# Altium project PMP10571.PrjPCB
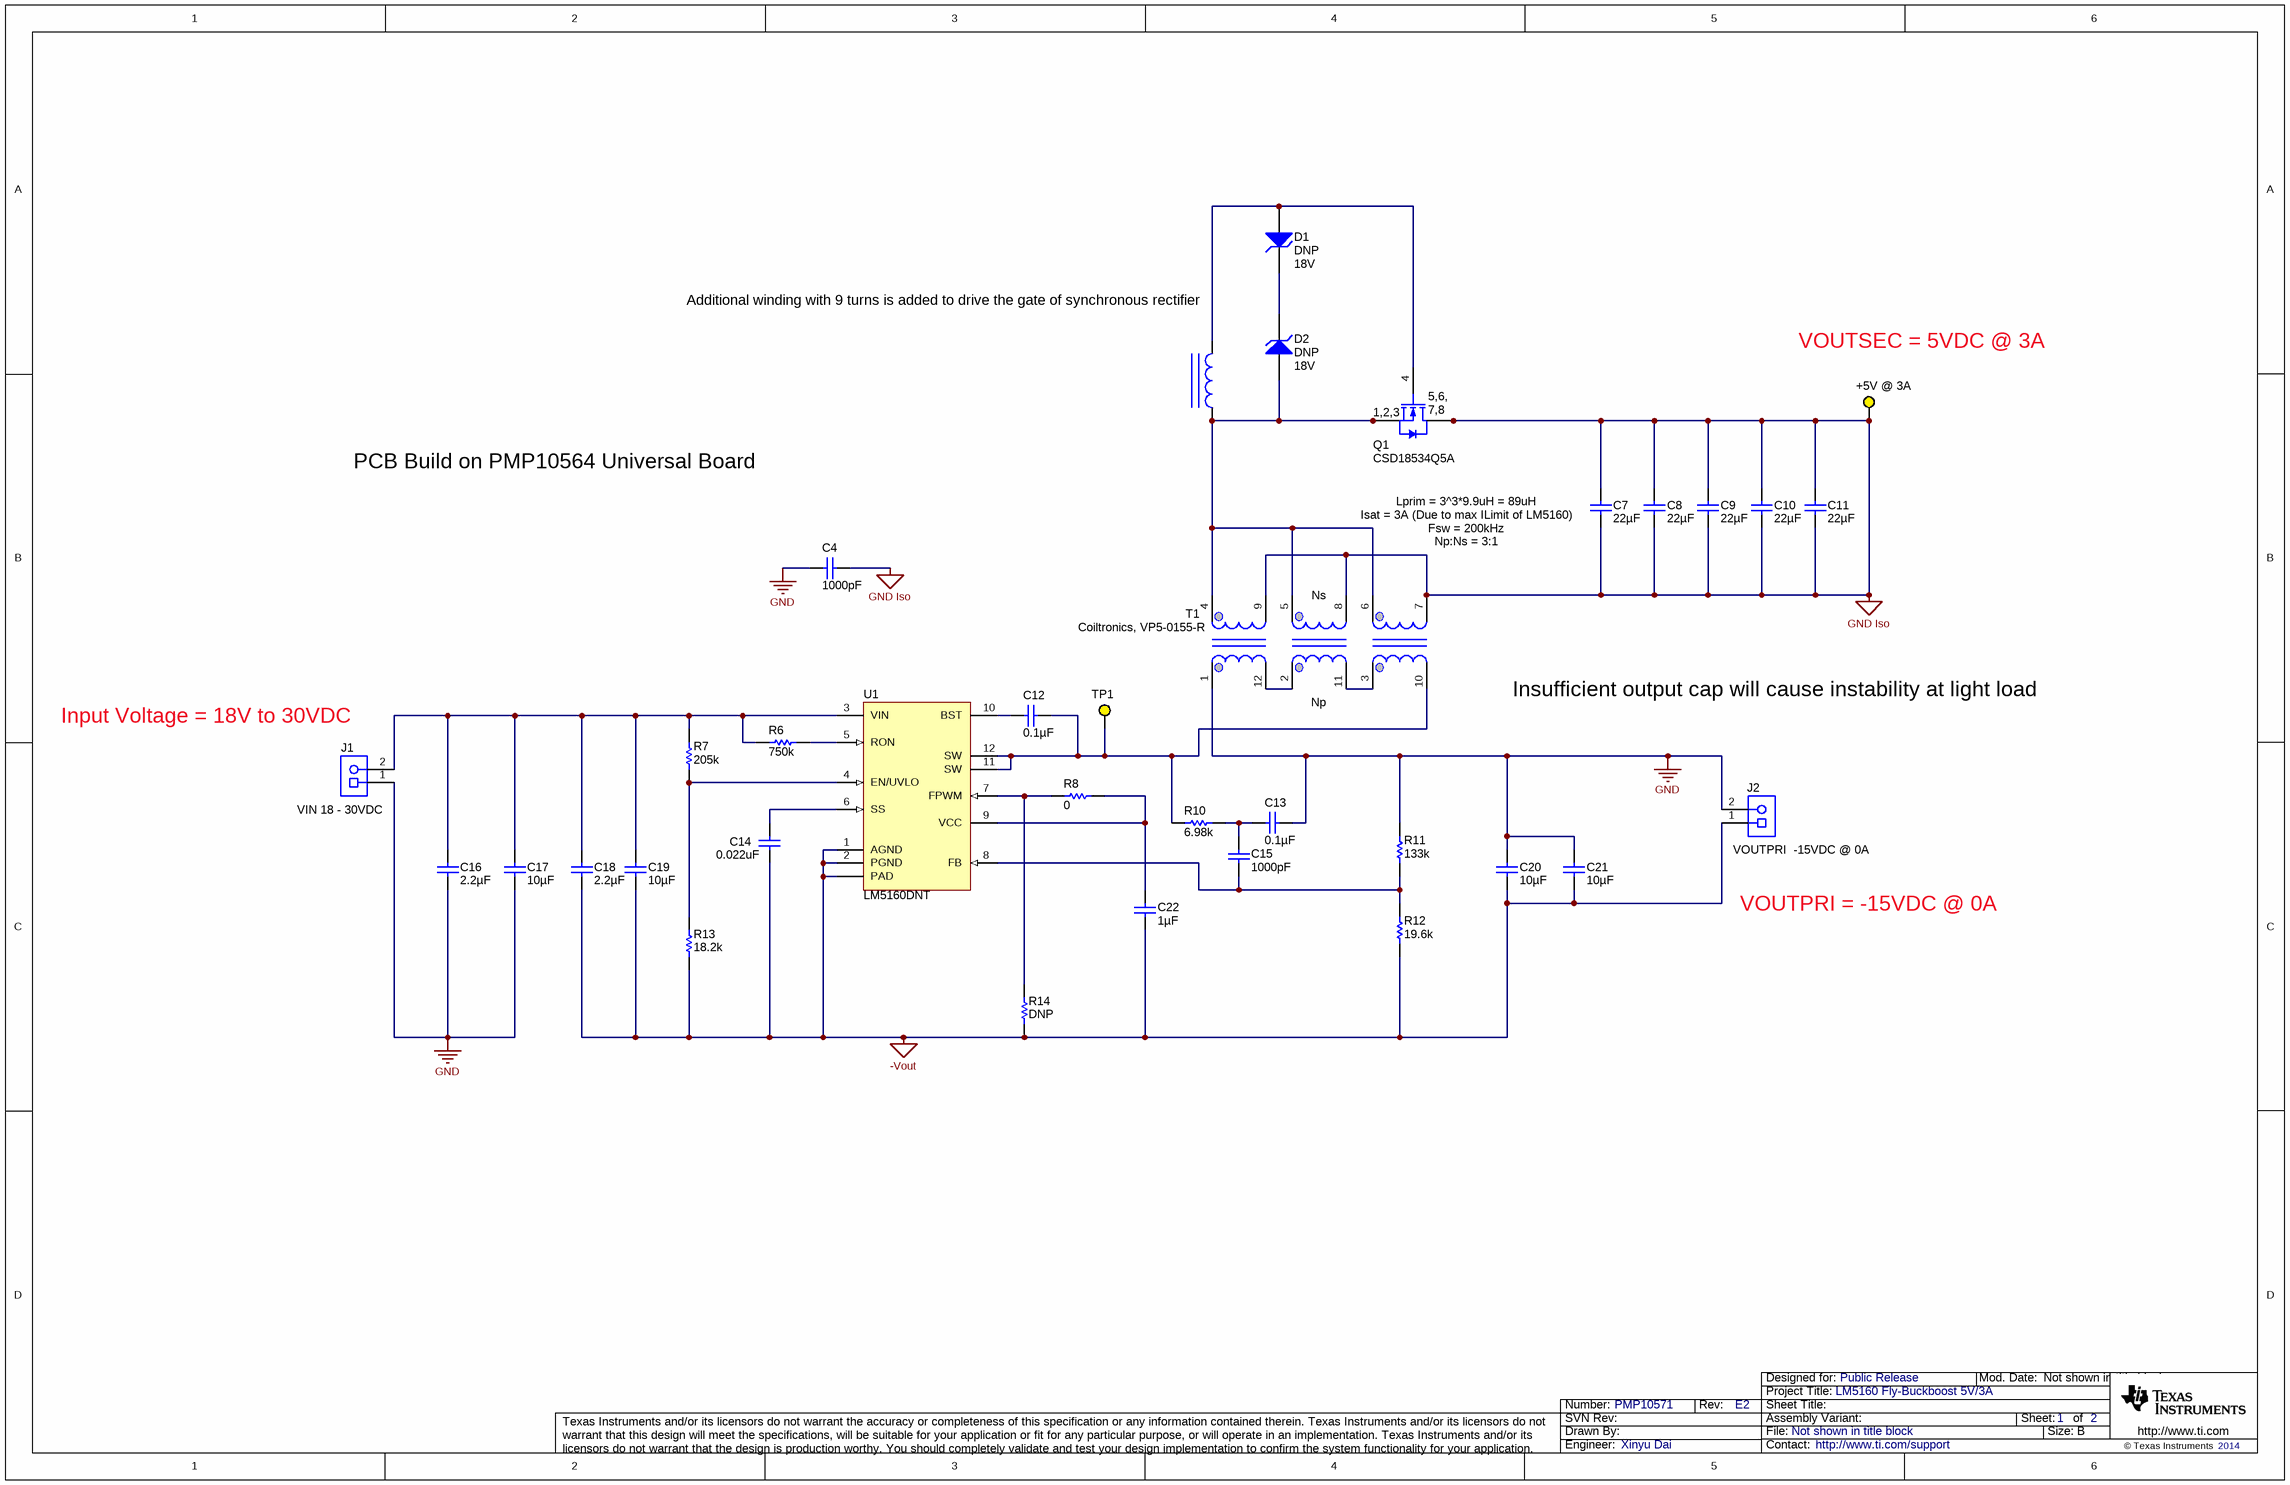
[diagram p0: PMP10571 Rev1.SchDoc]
TechSupport: http://www.ti.com/support; SCH_Rev: E2; PRJ_Title: LM5160 Fly-Buckboost 5V/3A; PRJ_Number: PMP10571; PRJ_Engineer: Xinyu Dai; PRJ_Customer: Public Release; PCB_Rev: E1; PCB_Layout: Hrag Kasparian; CopyrightYear: 2014
2 sheets, 54 parts. Net scope: global (net labels, ports and power ports of the same name join across sheets).
Board file: PMP10564.PcbDoc
Sheets:
  PMP10571 Rev1.SchDoc
  Hardware_ANSI-B.SchDoc

## Sheet PMP10571 Rev1.SchDoc
size 431 x 279 mm; Date: Not shown in title block; ApprovedBy: Not shown in title block; CheckedBy: Not shown in title block; Author: Not shown in title block; CompanyName: Not shown in title block; Engineer: Not shown in title block; Organization: Not shown in title block; Address1: Not shown in title block; Address2: Not shown in title block; Address3: Not shown in title block; Address4: Not shown in title block; DocumentNumber: 1; Revision: Use project parameter SCH_Rev; SheetNumber: 1; SheetTotal: 2; PageSetup: Record=PageOptions|CenterHorizontal=True|CenterVertical=True|PrintScale=1.00|XCorrection=1.00|YCorrection=1.00|PrintKind=0|BorderSize=5000000|LeftOffset=0|BottomOffset=0|Orientation=2|PaperLength=1000|PaperWidth=1000|Scale=100|PaperSource=15|PrintQuality=600|MediaType=1|DitherType=10|PaperKind=Letter|PrintScaleMode=1

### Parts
+5V_@_3A  5014  [Keystone5014]  (value not drawn)
C4  ValueDisplayed: 1000pF  [1206]  (hidden comment: VJ1206A102JXGAT5Z)
C7  ValueDisplayed: 22µF  [1210]  (hidden comment: GRM32ER71E226KE15L)
C8  ValueDisplayed: 22µF  [1210]  (hidden comment: GRM32ER71E226KE15L)
C9  ValueDisplayed: 22µF  [1210]  (hidden comment: GRM32ER71E226KE15L)
C10  ValueDisplayed: 22µF  [1210]  (hidden comment: GRM32ER71E226KE15L)
C11  ValueDisplayed: 22µF  [1210]  (hidden comment: GRM32ER71E226KE15L)
C12  ValueDisplayed: 0.1µF  [0603]  (hidden comment: C0603C104J3RAC)
C13  ValueDisplayed: 0.1µF  [0603]  (hidden comment: GRM188R72A104KA35D)
C14  ValueDisplayed: 0.022uF  [0603]  (hidden comment: GRM188R71C223KA01D)
C15  ValueDisplayed: 1000pF  [0603]  (hidden comment: GRM188R71E102KA01D)
C16  ValueDisplayed: 2.2µF  [1206]  (hidden comment: GRM31CR61H225KA88L)
C17  ValueDisplayed: 10µF  [1206_190]  (hidden comment: CL31A106KBHNNNE)
C18  ValueDisplayed: 2.2µF  [1206_190]  (hidden comment: GRM31CR72A225KA73L)
C19  ValueDisplayed: 10µF  [1206_190]  (hidden comment: CL31A106KBHNNNE)
C20  ValueDisplayed: 10µF  [1206_190]  (hidden comment: CL31A106KBHNNNE)
C21  ValueDisplayed: 10µF  [1206_190]  (hidden comment: CL31A106KBHNNNE)
C22  ValueDisplayed: 1µF  [0603]  (hidden comment: GRM188R71E105KA12D)
D1  DNP  value 18V  [SOD-123]
D2  DNP  value 18V  [SOD-123]
J1  1727010  [PhoenixConact_1727010]  (value not drawn)
J2  1727010  [PhoenixConact_1727010]  (value not drawn)
L?  CLF7045T-1R0N  [CLF7045]  (value not drawn)
Q1  CSD18534Q5A  [TRANS_NexFET_Q5A]
R6  ValueDisplayed: 750k  [0603]  (hidden comment: CRCW0603750KFKEA)
R7  ValueDisplayed: 205k  [0603]  (hidden comment: CRCW0603205KFKEA)
R8  value 0  [0805_HV]  (hidden comment: ERJ-6RQFR47V)
R10  ValueDisplayed: 6.98k  [0603]  (hidden comment: CRCW06036K98FKEA)
R11  ValueDisplayed: 133k  [0603]  (hidden comment: CRCW0603133KFKEA)
R12  ValueDisplayed: 19.6k  [0603]  (hidden comment: CRCW060319K6FKEA)
R13  value 18.2k  [0603]  (hidden comment: CRCW060318K2FKEA)
R14  DNP  [0805_HV]
T1  Coiltronics, VP5-0155-R  [VP5]
TP1  5014  [Keystone5014]  (value not drawn)
U1  LM5160DNT  [DNT0012B]

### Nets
-Vout: C14.2 C18.2 C19.2 C20.2 C21.2 C22.2 J2.1 R12.1 R13.1 R14.1 U1.1(AGND) U1.2(PGND) U1.13(PAD)
GND: C4.2 C13.1 C16.2 C17.2 C20.1 C21.1 J1.1 J2.2 R11.2 T1.1
GND Iso: +5V_@_3A.1 C4.1 C7.1 C7.2 C8.1 C8.2 C9.1 C9.2 C10.1 C10.2 C11.1 C11.2 Q1.5(D) Q1.6(D) Q1.7(D) Q1.8(D) Q1.9(D) T1.7 T1.8 T1.9
NetC12_1: C12.1 R10.1 T1.10 TP1.1 U1.11(SW) U1.12(SW)
NetC12_2: C12.2 U1.10(BST)
NetC13_2: C13.2 C15.1 R10.2
NetC14_1: C14.1 U1.6(SS)
NetC15_2: C15.2 R11.1 R12.2 U1.8(FB)
NetC16_1: C16.1 C17.1 C18.1 C19.1 J1.2 R6.1 R7.2 U1.3(VIN)
NetC22_1: C22.1 R8.1 U1.9(VCC)
NetD1_1: D1.1(K) D2.1(K)
NetD1_2: D1.2(A) L?.2 Q1.4(G)
NetD2_2: D2.2(A) L?.1 Q1.1(S) Q1.2(S) Q1.3(S) T1.4 T1.5 T1.6
NetR6_2: R6.2 U1.5(RON)
NetR7_1: R7.1 R13.2 U1.4(EN/UVLO)
NetR8_2: R8.2 R14.2 U1.7(FPWM)
NetT1_2: T1.2 T1.12
NetT1_3: T1.3 T1.11

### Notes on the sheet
- Additional winding with 9 turns is added to drive the gate of synchronous rectifier
- VOUTSEC = 5VDC @ 3A
- PCB Build on PMP10564 Universal Board
- Lprim = 3^3*9.9uH = 89uH
- (near C7) Isat = 3A (Due to max ILimit of LM5160)
- Fsw = 200kHz
- Np:Ns = 3:1
- (near T1) Ns
- (near T1) Np
- (near T1) Insufficient output cap will cause instability at light load
- (near J1) Input Voltage = 18V to 30VDC
- (near J1) VIN 18 - 30VDC
- (near J2) VOUTPRI  -15VDC @ 0A
- VOUTPRI = -15VDC @ 0A

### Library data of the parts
+5V_@_3A TP1 = 5014: Test Point, Multipurpose, Yellow, TH; Manufacturer: Keystone; CompType: Test Point Loop; U/M: EA
C4 = VJ1206A102JXGAT5Z: CAP, CERM, 1000pF, 1000V, +/-5%, C0G/NP0, 1206; Manufacturer: Vishay-Vitramon; Polarized: N; CompType: Capacitor; U/M: EA; Cap_F: 0.000000001; Tolerance_%: 5; Value1: Unknown; VDC_V: 1000; TaMin_C: -55; TaMax_C: 125
C7-C11 = GRM32ER71E226KE15L: CAP, CERM, 22 µF, 25 V, +/- 10%, X7R, 1210; Manufacturer: MuRata; Polarized: N; CompType: Capacitor; Value: 22uF; U/M: EA; Cap_F: 0.000022; Tolerance_%: 10; Value1: Unknown; VDC_V: 25; Value2: 25V; TaMin_C: -55; TaMax_C: 125
C12 = C0603C104J3RAC: CAP, CERM, 0.1uF, 25V, +/-5%, X7R, 0603; Manufacturer: Kemet; Polarized: N; CompType: Capacitor; U/M: EA; Cap_F: 0.0000001; Tolerance_%: 5; Value1: Unknown; VDC_V: 25; TaMin_C: -55; TaMax_C: 125
C13 = GRM188R72A104KA35D: CAP, CERM, 0.1 µF, 100 V, +/- 10%, X7R, 0603; Manufacturer: MuRata; Polarized: N; CompType: Capacitor; Value: 0.1uF; U/M: EA; Cap_F: 0.0000001; Tolerance_%: 10; Value1: Unknown; VDC_V: 100; Value2: 100V; TaMin_C: -55; TaMax_C: 125
C14 = GRM188R71C223KA01D: CAP, CERM, 0.022uF, 16V, +/-10%, X7R, 0603; Manufacturer: MuRata; Polarized: N; CompType: Capacitor; U/M: EA; Cap_F: 0.000000022; Tolerance_%: 10; Value1: Unknown; VDC_V: 16; TaMin_C: -55; TaMax_C: 125
C15 = GRM188R71E102KA01D: CAP, CERM, 1000 pF, 25 V, +/- 10%, X7R, 0603; Manufacturer: MuRata; Polarized: N; CompType: Capacitor; Value: 1000pF; U/M: EA; Cap_F: 0.000000001; Tolerance_%: 10; Value1: Unknown; VDC_V: 25; Value2: 25V; TaMin_C: -55; TaMax_C: 125
C16 = GRM31CR61H225KA88L: CAP, CERM, 2.2uF, 50V, +/-10%, X5R, 1206; Manufacturer: MuRata; Polarized: N; CompType: Capacitor; U/M: EA; Cap_F: 0.0000022; Tolerance_%: 10; Value1: Unknown; VDC_V: 50; TaMin_C: -55; TaMax_C: 85
C17 C19-C21 = CL31A106KBHNNNE: CAP, CERM, 10 µF, 50 V, +/- 10%, X5R, 1206_190; Manufacturer: Samsung; Polarized: N; CompType: Capacitor; Value: 10uF; U/M: EA; Cap_F: 0.00001; Tolerance_%: 10; Value1: Unknown; VDC_V: 50; Value2: 50V; TaMin_C: -55; TaMax_C: 85
C18 = GRM31CR72A225KA73L: CAP, CERM, 2.2uF, 100V, +/-10%, X7R, 1206_190; Manufacturer: MuRata; Polarized: N; CompType: Capacitor; U/M: EA; Cap_F: 0.0000022; Tolerance_%: 10; Value1: Unknown; VDC_V: 100; TaMin_C: -55; TaMax_C: 125
C22 = GRM188R71E105KA12D: CAP, CERM, 1uF, 25V, +/-10%, X7R, 0603; Manufacturer: MuRata; Polarized: N; CompType: Capacitor; U/M: EA; Cap_F: 0.000001; Tolerance_%: 10; Value1: Unknown; VDC_V: 25; TaMin_C: -55; TaMax_C: 125
D1 D2 = MMSZ4705-V: Diode, Zener, 18 V, 500 mW, SOD-123; Manufacturer: Vishay-Semiconductor; SymbolCreator: a0412235; U/M: EA; Power_W: 0.5; Vz_V: 18; Value1: 0.5W; RJA_CperW: 67
J1 J2 = 1727010: Conn Term Block, 2POS, 3.81mm, TH; Manufacturer: Phoenix Contact; SymbolCreator: a0412235; Value: 2x1; CompType: Terminal Block; U/M: EA
L? = CLF7045T-1R0N: Inductor, Shielded, Ferrite, 1 µH, 8.9 A, 0.01 ohm, SMD; Manufacturer: TDK; Value: 1uH; Ind_H: 1.0E-6; ValueDisplayed: 1µH; Imax_A: 8.9; Irms: 5.2A @ 30C rise; Isat: 8.9A @ 10% inductance drop; DCR_ohm: 0.01; Value2: 8.9A
Q1 = CSD18534Q5A: MOSFET, N-CH, 60 V, 50 A, SON 5x6mm; Manufacturer: Texas Instruments; Alternate Manufacturer: None; U/M: EA; ChType: N; Value: 60V; VdsMax_V: 60; Value1: 0.0098 ohm; Rdson45_ohm: 0.0098; Value2: 22 nC; QgTyp_nC: 22; Vgs_V: 2.3; IdsMax_A: 50
R6 = CRCW0603750KFKEA: RES, 750 k, 1%, 0.1 W, 0603; Manufacturer: Vishay-Dale; CompType: Resistor; Value: 750k; Res_ohm: 750000; Tolerance_%: 1; Power_W: 0.1; Value2: 0.1W; VDC_V: 75; TempCo: 100 ppm/C; EIA_Code: E96; U/M: EA
R7 = CRCW0603205KFKEA: RES, 205 k, 1%, 0.1 W, 0603; Manufacturer: Vishay-Dale; CompType: Resistor; Value: 205k; Res_ohm: 205000; Tolerance_%: 1; Power_W: 0.1; Value2: 0.1W; VDC_V: 75; TempCo: 100 ppm/C; EIA_Code: E96; U/M: EA
R8 R14 = ERJ-6RQFR47V: RES, 0.47 ohm, 1%, 0.125W, 0805; Manufacturer: Panasonic; CompType: Resistor; Res_ohm: 0.47; Value_Code: R470; Tolerance_%: 1; Power_W: 0.125; TempCo: 250 ppm/C; EIA_Code: E96; U/M: EA
R10 = CRCW06036K98FKEA: RES, 6.98 k, 1%, 0.1 W, 0603; Manufacturer: Vishay-Dale; CompType: Resistor; Value: 6.98k; Res_ohm: 6980; Value_Code: 6k98; Tolerance_%: 1; Power_W: 0.1; Value2: 0.1W; VDC_V: 75; TempCo: 100 ppm/C; EIA_Code: E96; U/M: EA
R11 = CRCW0603133KFKEA: RES, 133 k, 1%, 0.1 W, 0603; Manufacturer: Vishay-Dale; CompType: Resistor; Value: 133k; Res_ohm: 133000; Tolerance_%: 1; Power_W: 0.1; Value2: 0.1W; VDC_V: 75; TempCo: 100 ppm/C; EIA_Code: E96; U/M: EA
R12 = CRCW060319K6FKEA: RES, 19.6 k, 1%, 0.1 W, 0603; Manufacturer: Vishay-Dale; CompType: Resistor; Value: 19.6k; Res_ohm: 19600; Value_Code: 19k6; Tolerance_%: 1; Power_W: 0.1; Value2: 0.1W; VDC_V: 75; TempCo: 100 ppm/C; EIA_Code: E96; U/M: EA
R13 = CRCW060318K2FKEA: RES, 18.2k ohm, 1%, 0.1W, 0603; Manufacturer: Vishay-Dale; CompType: Resistor; Res_ohm: 18200; Value_Code: 18k2; Tolerance_%: 1; Power_W: 0.1; VDC_V: 75; TempCo: 100 ppm/C; EIA_Code: E96; U/M: EA
T1 = VP5XFMR
U1 = LM5160DNT: Wide Input 65V, 1.5A Synchronous Step-Down DC-DC Converter, DNT0012B; Manufacturer: Texas Instruments; Alternate Manufacturer: None; SymbolCreator: a0411947; CompType: IC; U/M: EA

## Sheet Hardware_ANSI-B.SchDoc
size 431 x 279 mm; Date: Not shown in title block; ApprovedBy: Not shown in title block; CheckedBy: Not shown in title block; Author: Not shown in title block; CompanyName: Not shown in title block; Engineer: Not shown in title block; Organization: Not shown in title block; Address1: Not shown in title block; Address2: Not shown in title block; Address3: Not shown in title block; Address4: Not shown in title block; DocumentNumber: 2; Revision: Use project parameter SCH_Rev; SheetNumber: 2; SheetTotal: 2; PageSetup: Record=PageOptions|CenterHorizontal=True|CenterVertical=True|PrintScale=1.00|XCorrection=1.00|YCorrection=1.00|PrintKind=0|BorderSize=5000000|LeftOffset=0|BottomOffset=0|Orientation=2|PaperLength=1000|PaperWidth=1000|Scale=100|PaperSource=15|PrintQuality=600|MediaType=1|DitherType=10|PaperKind=Letter|PrintScaleMode=1
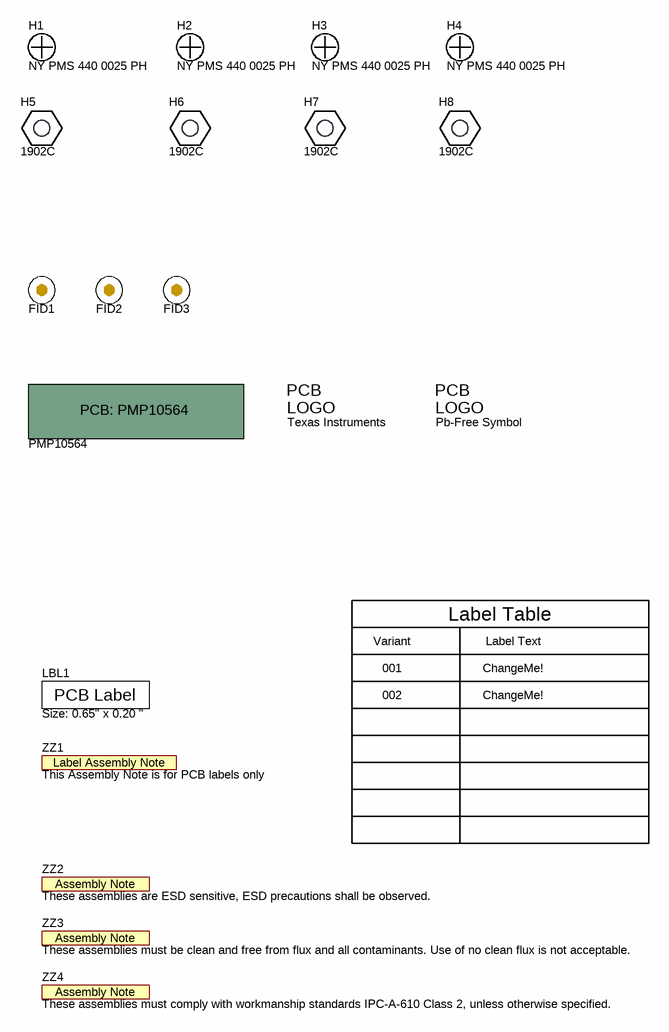
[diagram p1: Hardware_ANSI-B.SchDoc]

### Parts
!PCB  PMP10564  (mechanical)
FID1  Fiducial  [Fiducial10-20]  (value not drawn)
FID2  Fiducial  [Fiducial10-20]  (value not drawn)
FID3  Fiducial  [Fiducial10-20]  (value not drawn)
H1  NY PMS 440 0025 PH  [NY PMS 440 0025 PH]
H2  NY PMS 440 0025 PH  [NY PMS 440 0025 PH]
H3  NY PMS 440 0025 PH  [NY PMS 440 0025 PH]
H4  NY PMS 440 0025 PH  [NY PMS 440 0025 PH]
H5  1902C  [Keystone_1902C]
H6  1902C  [Keystone_1902C]
H7  1902C  [Keystone_1902C]
H8  1902C  [Keystone_1902C]
LBL1  Size: 0.65" x 0.20 "  [Label_650x200]
Logo1  Texas Instruments  [TI_Stacked_SolderMask_Small]  (no BOM)
Logo2  Pb-Free Symbol  [Pb-Free_Overlay_Small]  (no BOM)
ZZ1  This Assembly Note is for PCB labels only  [AssemblyNoteLabel]  (no BOM)
ZZ2  These assemblies are ESD sensitive, ESD precautions shall be observed.  [AssemblyNote]  (no BOM)
ZZ3  These assemblies must be clean and free from flux and all contaminants. Use of no clean flux is not acceptable.  [AssemblyNote]  (no BOM)
ZZ4  These assemblies must comply with workmanship standards IPC-A-610 Class 2, unless otherwise specified.  [AssemblyNote]  (no BOM)

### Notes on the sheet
- Variant
- Label Table
- Label Text
- 001
- 002
- ChangeMe!

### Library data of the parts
!PCB = PCB_OtherProject: Manufacturer: Any; SymbolCreator: a0412235; CompType: PCB; U/M: EA
FID1-FID3 = Fiducial: Fiducial mark.  There is nothing to buy or mount.; SymbolCreator: codlsc
H1-H4 = NY PMS 440 0025 PH: Machine Screw, Round, #4-40 x 1/4, Nylon, Philips panhead; Manufacturer: B&F Fastener Supply; CompType: Hardware; SymbolCreator: codlsc; U/M: EA
H5-H8 = 1902C: Standoff, Hex, 0.5"L #4-40 Nylon; Manufacturer: Keystone; CompType: Hardware; SymbolCreator: a0412235
LBL1 = THT-14-423-10: Thermal Transfer Printable Labels, 0.650" W x 0.200" H - 10,000 per roll; Manufacturer: Brady; SymbolCreator: a0412235; CompType: Label
Logo1 = TI_Logo: Texas Instrument Corporate Signature; SymbolCreator: a0412235
Logo2 = Pb-Free: SymbolCreator: a0412235
ZZ1 = AssemblyNoteLabel: SymbolCreator: a0412235
ZZ2-ZZ4 = AssemblyNote: SymbolCreator: codlsc

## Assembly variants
001: not fitted D1 D2 FID1 FID2 FID3 R14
